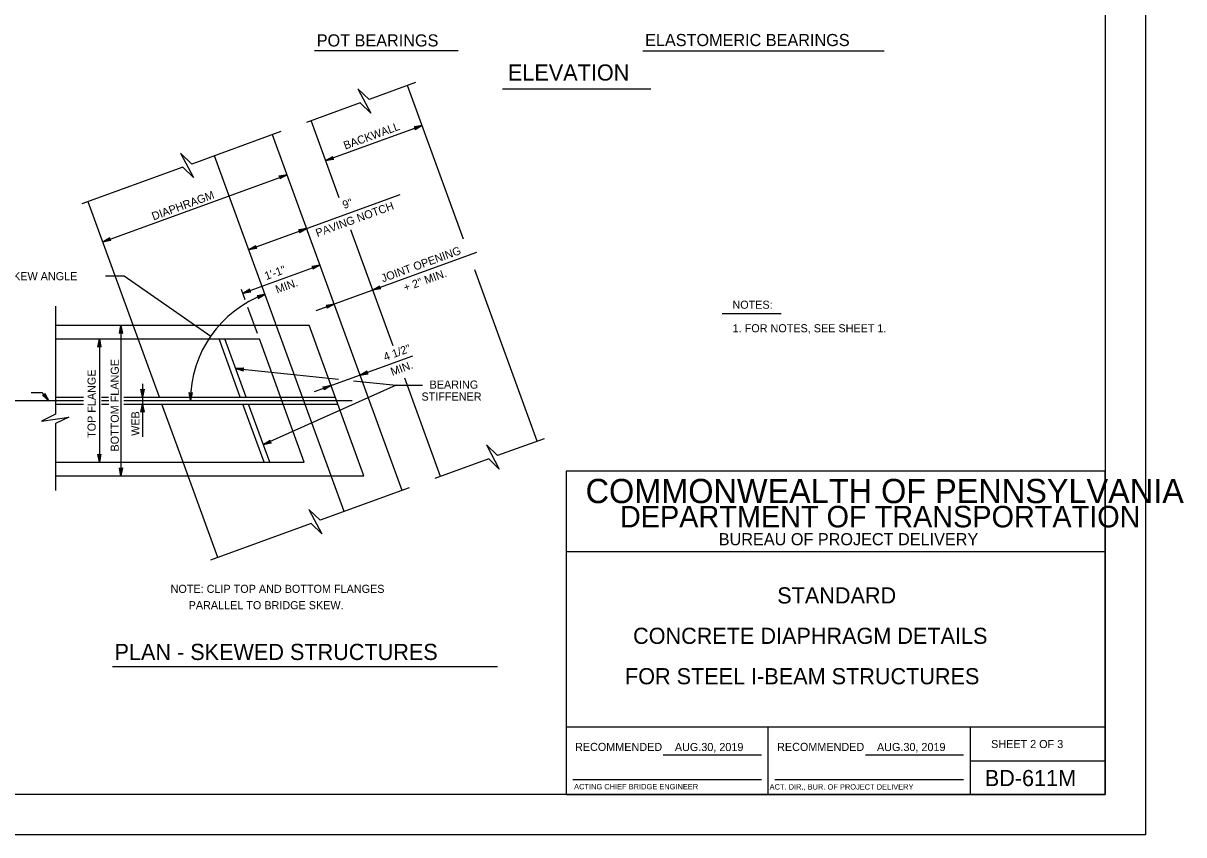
# Model space of a CAD drawing. Extents: x 640009 to 641706, y 298547 to 299735.
# Drawn here: x 641275 to 641705.7, y 299141.2 to 299442.5 of the extents above; entities that cross this region are included whole.
import ezdxf

# ---------------------------------------------------------------- set-up
doc = ezdxf.new("R2010")
doc.units = 0
doc.layers.add('1', color=7, linetype='Continuous')
doc.layers.add('PLT-BNDY', color=7, linetype='Continuous')

msp = doc.modelspace()

# ---------------------------------------------------------------- linework, layer by layer
at = {"layer": '1'}
for p, q in [((641676.47, 299720.17), (641676.47, 299156.17)), ((641676.47, 299720.17), (641676.47, 299156.17)), ((641383.1, 299432.38), (641436.38, 299432.38)), ((641504.95, 299432.23), (641594.55, 299432.23)), ((641420.65, 299420.44), (641403.4, 299414.16)), ((641438.4, 299362.3), (641417.64, 299419.34)), ((641452.84, 299418.18), (641507.99, 299418.18)), ((641400.1, 299412.96), (641380.09, 299405.67)), ((641392.26, 299377.67), (641381.84, 299406.31)), ((641370.64, 299402.24), (641337.56, 299390.2)), ((641387.24, 299391.46), (641423.05, 299404.49)), ((641415.59, 299269.02), (641367.52, 299401.1)), ((641394.11, 299261.2), (641346.04, 299393.28)), ((641334.25, 299388.99), (641296.82, 299375.37)), ((641304.56, 299361.36), (641372.92, 299386.25)), ((641317.7, 299325.25), (641299.15, 299376.22)), ((641358.72, 299358.43), (641414.96, 299378.9)), ((641412.26, 299322.72), (641396.6, 299365.75)), ((641383.76, 299335.82), (641443.42, 299357.53)), ((641356.5, 299342.26), (641385.14, 299352.69)), ((641465.71, 299287.26), (641442.57, 299350.86)), ((641305.6, 299348.64), (641312.45, 299348.64)), ((641312.45, 299348.64), (641344.6, 299326.33)), ((641357.4, 299339.79), (641356.01, 299343.59)), ((641286.98, 299337.48), (641286.98, 299297.33)), ((641361.95, 299327.27), (641358.43, 299336.96)), ((641534.42, 299334.77), (641556.28, 299334.77)), ((641286.98, 299330.32), (641381.11, 299330.32)), ((641311.29, 299330.32), (641311.29, 299274.44)), ((641401.45, 299274.44), (641381.11, 299330.32)), ((641286.98, 299325.25), (641362.69, 299325.25)), ((641303.29, 299325.25), (641303.29, 299279.52)), ((641325.56, 299303.65), (641317.7, 299325.25)), ((641355.59, 299303.65), (641347.74, 299325.25)), ((641357.72, 299303.65), (641349.86, 299325.25)), ((641379.33, 299279.52), (641362.69, 299325.25)), ((641383.16, 299305.7), (641419.57, 299318.95)), ((641353.87, 299314.23), (641392.06, 299310.28)), ((641319.29, 299308.56), (641319.29, 299288.88)), ((641413.39, 299308.08), (641364.14, 299286.03)), ((641397.61, 299309.71), (641413.39, 299308.08)), ((641413.39, 299308.08), (641423.18, 299308.08)), ((641429.91, 299274.23), (641416.62, 299310.75)), ((641277.98, 299305.41), (641281.98, 299305.41)), ((641281.98, 299305.41), (641284.45, 299302.38)), ((641286.98, 299303.65), (641297.34, 299303.65)), ((641304.12, 299303.65), (641306.71, 299303.65)), ((641312.42, 299303.65), (641370.55, 299303.65)), ((641370.55, 299303.65), (641390.82, 299303.65)), ((641262.69, 299302.38), (641297.34, 299302.38)), ((641286.98, 299301.11), (641297.34, 299301.11)), ((641304.12, 299302.38), (641306.84, 299302.38)), ((641304.12, 299301.11), (641306.84, 299301.11)), ((641312.42, 299302.38), (641397.05, 299302.38)), ((641312.42, 299301.11), (641371.47, 299301.11)), ((641334.35, 299279.52), (641326.49, 299301.11)), ((641364.38, 299279.52), (641356.52, 299301.11)), ((641366.51, 299279.52), (641358.65, 299301.11)), ((641371.47, 299301.11), (641391.75, 299301.11)), ((641286.98, 299293.81), (641286.98, 299269.04)), ((641468.3, 299288.2), (641451.06, 299281.93)), ((641286.98, 299279.52), (641379.33, 299279.52)), ((641347.23, 299244.13), (641334.35, 299279.52)), ((641447.75, 299280.72), (641427.74, 299273.44)), ((641286.98, 299274.44), (641401.45, 299274.44)), ((641676.47, 299276.17), (641476.47, 299276.17)), ((641476.47, 299276.17), (641476.47, 299156.17)), ((641676.47, 299276.17), (641476.47, 299276.17)), ((641476.47, 299276.17), (641476.47, 299156.17)), ((641676.47, 299156.17), (641676.47, 299276.17)), ((641676.47, 299156.17), (641676.47, 299276.17)), ((641418.3, 299270), (641385.21, 299257.96)), ((641381.91, 299256.76), (641344.47, 299243.13)), ((641676.47, 299246.17), (641476.47, 299246.17)), ((641676.47, 299246.17), (641476.47, 299246.17)), ((641308.12, 299203.66), (641451.01, 299203.66)), ((641676.47, 299181.17), (641476.47, 299181.17)), ((641676.47, 299181.17), (641476.47, 299181.17)), ((641551.47, 299156.17), (641551.47, 299181.17)), ((641626.47, 299181.17), (641626.47, 299156.17)), ((641626.47, 299181.17), (641626.47, 299156.17)), ((641512.56, 299170.89), (641548.97, 299170.89)), ((641587.56, 299170.89), (641623.97, 299170.89)), ((641626.47, 299168.67), (641676.47, 299168.67)), ((641626.47, 299168.67), (641676.47, 299168.67)), ((641478.97, 299161.67), (641548.97, 299161.67)), ((641553.97, 299161.67), (641623.97, 299161.67)), ((641676.47, 299156.17), (640890.47, 299156.17)), ((641676.47, 299156.17), (640890.47, 299156.17)), ((641476.47, 299156.17), (641676.47, 299156.17)), ((641476.47, 299156.17), (641676.47, 299156.17))]:
    msp.add_line(p, q, dxfattribs=at)
for points in [[(641403.4, 299414.16), (641399.25, 299418.17), (641404.01, 299409.1), (641400.1, 299412.96)], [(641423.05, 299404.49), (641420.43, 299402.95), (641420.52, 299403.06), (641420.6, 299403.17), (641420.62, 299403.29), (641420.64, 299403.4), (641420.62, 299403.5), (641420.6, 299403.6), (641420.55, 299403.69), (641420.5, 299403.78), (641420.41, 299403.85), (641420.32, 299403.93), (641420.19, 299403.96), (641420.05, 299404), (641423.05, 299404.49), (641420.19, 299403.96), (641420.32, 299403.93), (641423.05, 299404.49), (641420.41, 299403.85), (641420.5, 299403.78), (641423.05, 299404.49), (641420.55, 299403.69), (641420.6, 299403.6), (641423.05, 299404.49), (641420.62, 299403.5), (641420.64, 299403.4), (641423.05, 299404.49), (641420.62, 299403.29), (641420.6, 299403.17), (641423.05, 299404.49), (641420.52, 299403.06)], [(641337.56, 299390.2), (641333.4, 299394.2), (641338.17, 299385.14), (641334.25, 299388.99)], [(641387.24, 299391.46), (641389.86, 299393.01), (641389.77, 299392.89), (641389.69, 299392.78), (641389.67, 299392.66), (641389.65, 299392.55), (641389.67, 299392.45), (641389.69, 299392.35), (641389.74, 299392.26), (641389.79, 299392.17), (641389.88, 299392.1), (641389.97, 299392.03), (641390.1, 299391.99), (641390.24, 299391.95), (641387.24, 299391.46), (641390.1, 299391.99), (641389.97, 299392.03), (641387.24, 299391.46), (641389.88, 299392.1), (641389.79, 299392.17), (641387.24, 299391.46), (641389.74, 299392.26), (641389.69, 299392.35), (641387.24, 299391.46), (641389.67, 299392.45), (641389.65, 299392.55), (641387.24, 299391.46), (641389.67, 299392.66), (641389.69, 299392.78), (641387.24, 299391.46), (641389.77, 299392.89)], [(641372.92, 299386.25), (641370.31, 299384.7), (641370.39, 299384.82), (641370.47, 299384.93), (641370.49, 299385.04), (641370.52, 299385.16), (641370.5, 299385.26), (641370.48, 299385.36), (641370.43, 299385.45), (641370.38, 299385.53), (641370.29, 299385.61), (641370.2, 299385.68), (641370.06, 299385.72), (641369.93, 299385.75), (641372.92, 299386.25), (641370.06, 299385.72), (641370.2, 299385.68), (641372.92, 299386.25), (641370.29, 299385.61), (641370.38, 299385.53), (641372.92, 299386.25), (641370.43, 299385.45), (641370.48, 299385.36), (641372.92, 299386.25), (641370.5, 299385.26), (641370.52, 299385.16), (641372.92, 299386.25), (641370.49, 299385.04), (641370.47, 299384.93), (641372.92, 299386.25), (641370.39, 299384.82)], [(641380.2, 299366.25), (641377.59, 299364.71), (641377.67, 299364.82), (641377.75, 299364.93), (641377.77, 299365.05), (641377.79, 299365.16), (641377.78, 299365.26), (641377.76, 299365.36), (641377.71, 299365.45), (641377.66, 299365.54), (641377.57, 299365.61), (641377.48, 299365.69), (641377.34, 299365.72), (641377.21, 299365.76), (641380.2, 299366.25), (641377.34, 299365.72), (641377.48, 299365.69), (641380.2, 299366.25), (641377.57, 299365.61), (641377.66, 299365.54), (641380.2, 299366.25), (641377.71, 299365.45), (641377.76, 299365.36), (641380.2, 299366.25), (641377.78, 299365.26), (641377.79, 299365.16), (641380.2, 299366.25), (641377.77, 299365.05), (641377.75, 299364.93), (641380.2, 299366.25), (641377.67, 299364.82)], [(641304.56, 299361.36), (641307.17, 299362.91), (641307.09, 299362.8), (641307.01, 299362.68), (641306.99, 299362.57), (641306.96, 299362.45), (641306.98, 299362.35), (641307, 299362.25), (641307.05, 299362.17), (641307.1, 299362.08), (641307.19, 299362), (641307.28, 299361.93), (641307.42, 299361.9), (641307.55, 299361.86), (641304.56, 299361.36), (641307.42, 299361.9), (641307.28, 299361.93), (641304.56, 299361.36), (641307.19, 299362), (641307.1, 299362.08), (641304.56, 299361.36), (641307.05, 299362.17), (641307, 299362.25), (641304.56, 299361.36), (641306.98, 299362.35), (641306.96, 299362.45), (641304.56, 299361.36), (641306.99, 299362.57), (641307.01, 299362.68), (641304.56, 299361.36), (641307.09, 299362.8)], [(641358.72, 299358.43), (641361.33, 299359.98), (641361.25, 299359.86), (641361.17, 299359.75), (641361.15, 299359.64), (641361.13, 299359.52), (641361.14, 299359.42), (641361.16, 299359.32), (641361.21, 299359.23), (641361.26, 299359.15), (641361.35, 299359.07), (641361.44, 299359), (641361.58, 299358.96), (641361.71, 299358.93), (641358.72, 299358.43), (641361.58, 299358.96), (641361.44, 299359), (641358.72, 299358.43), (641361.35, 299359.07), (641361.26, 299359.15), (641358.72, 299358.43), (641361.21, 299359.23), (641361.16, 299359.32), (641358.72, 299358.43), (641361.14, 299359.42), (641361.13, 299359.52), (641358.72, 299358.43), (641361.15, 299359.64), (641361.17, 299359.75), (641358.72, 299358.43), (641361.25, 299359.86)], [(641385.14, 299352.69), (641382.53, 299351.14), (641382.61, 299351.26), (641382.69, 299351.37), (641382.71, 299351.48), (641382.73, 299351.6), (641382.71, 299351.7), (641382.69, 299351.8), (641382.64, 299351.89), (641382.59, 299351.97), (641382.5, 299352.05), (641382.41, 299352.12), (641382.28, 299352.16), (641382.14, 299352.19), (641385.14, 299352.69), (641382.28, 299352.16), (641382.41, 299352.12), (641385.14, 299352.69), (641382.5, 299352.05), (641382.59, 299351.97), (641385.14, 299352.69), (641382.64, 299351.89), (641382.69, 299351.8), (641385.14, 299352.69), (641382.71, 299351.7), (641382.73, 299351.6), (641385.14, 299352.69), (641382.71, 299351.48), (641382.69, 299351.37), (641385.14, 299352.69), (641382.61, 299351.26)], [(641356.5, 299342.26), (641359.11, 299343.81), (641359.03, 299343.69), (641358.95, 299343.58), (641358.92, 299343.47), (641358.9, 299343.35), (641358.92, 299343.25), (641358.94, 299343.15), (641358.99, 299343.06), (641359.04, 299342.98), (641359.13, 299342.9), (641359.22, 299342.83), (641359.35, 299342.79), (641359.49, 299342.76), (641356.5, 299342.26), (641359.35, 299342.79), (641359.22, 299342.83), (641356.5, 299342.26), (641359.13, 299342.9), (641359.04, 299342.98), (641356.5, 299342.26), (641358.99, 299343.06), (641358.94, 299343.15), (641356.5, 299342.26), (641358.92, 299343.25), (641358.9, 299343.35), (641356.5, 299342.26), (641358.92, 299343.47), (641358.95, 299343.58), (641356.5, 299342.26), (641359.03, 299343.69)], [(641364.75, 299341.86), (641362.21, 299340.21), (641362.28, 299340.33), (641362.36, 299340.44), (641362.37, 299340.56), (641362.39, 299340.67), (641362.37, 299340.77), (641362.35, 299340.87), (641362.29, 299340.96), (641362.24, 299341.04), (641362.15, 299341.11), (641362.05, 299341.18), (641361.92, 299341.21), (641361.78, 299341.24), (641364.75, 299341.86), (641361.92, 299341.21), (641362.05, 299341.18), (641364.75, 299341.86), (641362.15, 299341.11), (641362.24, 299341.04), (641364.75, 299341.86), (641362.29, 299340.96), (641362.35, 299340.87), (641364.75, 299341.86), (641362.37, 299340.77), (641362.39, 299340.67), (641364.75, 299341.86), (641362.37, 299340.56), (641362.36, 299340.44), (641364.75, 299341.86), (641362.28, 299340.33)], [(641404.72, 299343.45), (641407.33, 299344.99), (641407.25, 299344.88), (641407.17, 299344.76), (641407.15, 299344.65), (641407.13, 299344.54), (641407.14, 299344.44), (641407.16, 299344.34), (641407.21, 299344.25), (641407.26, 299344.16), (641407.35, 299344.09), (641407.44, 299344.01), (641407.58, 299343.98), (641407.71, 299343.94), (641404.72, 299343.45), (641407.58, 299343.98), (641407.44, 299344.01), (641404.72, 299343.45), (641407.35, 299344.09), (641407.26, 299344.16), (641404.72, 299343.45), (641407.21, 299344.25), (641407.16, 299344.34), (641404.72, 299343.45), (641407.14, 299344.44), (641407.13, 299344.54), (641404.72, 299343.45), (641407.15, 299344.65), (641407.17, 299344.76), (641404.72, 299343.45), (641407.25, 299344.88)], [(641390.4, 299338.23), (641387.79, 299336.69), (641387.87, 299336.8), (641387.95, 299336.92), (641387.97, 299337.03), (641387.99, 299337.15), (641387.97, 299337.25), (641387.95, 299337.35), (641387.9, 299337.43), (641387.85, 299337.52), (641387.76, 299337.6), (641387.67, 299337.67), (641387.54, 299337.7), (641387.4, 299337.74), (641390.4, 299338.23), (641387.54, 299337.7), (641387.67, 299337.67), (641390.4, 299338.23), (641387.76, 299337.6), (641387.85, 299337.52), (641390.4, 299338.23), (641387.9, 299337.43), (641387.95, 299337.35), (641390.4, 299338.23), (641387.97, 299337.25), (641387.99, 299337.15), (641390.4, 299338.23), (641387.97, 299337.03), (641387.95, 299336.92), (641390.4, 299338.23), (641387.87, 299336.8)], [(641311.29, 299330.32), (641311.85, 299327.34), (641311.77, 299327.46), (641311.69, 299327.57), (641311.59, 299327.63), (641311.49, 299327.69), (641311.39, 299327.71), (641311.29, 299327.72), (641311.19, 299327.71), (641311.09, 299327.69), (641310.99, 299327.63), (641310.89, 299327.57), (641310.81, 299327.46), (641310.73, 299327.34), (641311.29, 299330.32), (641310.81, 299327.46), (641310.89, 299327.57), (641311.29, 299330.32), (641310.99, 299327.63), (641311.09, 299327.69), (641311.29, 299330.32), (641311.19, 299327.71), (641311.29, 299327.72), (641311.29, 299330.32), (641311.39, 299327.71), (641311.49, 299327.69), (641311.29, 299330.32), (641311.59, 299327.63), (641311.69, 299327.57), (641311.29, 299330.32), (641311.77, 299327.46)], [(641303.29, 299325.25), (641303.85, 299322.26), (641303.77, 299322.38), (641303.69, 299322.49), (641303.59, 299322.55), (641303.49, 299322.61), (641303.39, 299322.63), (641303.29, 299322.65), (641303.19, 299322.63), (641303.09, 299322.61), (641302.99, 299322.55), (641302.89, 299322.49), (641302.81, 299322.38), (641302.73, 299322.26), (641303.29, 299325.25), (641302.81, 299322.38), (641302.89, 299322.49), (641303.29, 299325.25), (641302.99, 299322.55), (641303.09, 299322.61), (641303.29, 299325.25), (641303.19, 299322.63), (641303.29, 299322.65), (641303.29, 299325.25), (641303.39, 299322.63), (641303.49, 299322.61), (641303.29, 299325.25), (641303.59, 299322.55), (641303.69, 299322.49), (641303.29, 299325.25), (641303.77, 299322.38)], [(641353.87, 299314.23), (641356.9, 299314.44), (641356.78, 299314.37), (641356.65, 299314.31), (641356.58, 299314.21), (641356.51, 299314.12), (641356.48, 299314.02), (641356.46, 299313.93), (641356.46, 299313.83), (641356.47, 299313.72), (641356.51, 299313.62), (641356.56, 299313.51), (641356.67, 299313.42), (641356.77, 299313.33), (641353.87, 299314.23), (641356.67, 299313.42), (641356.56, 299313.51), (641353.87, 299314.23), (641356.51, 299313.62), (641356.47, 299313.72), (641353.87, 299314.23), (641356.46, 299313.83), (641356.46, 299313.93), (641353.87, 299314.23), (641356.48, 299314.02), (641356.51, 299314.12), (641353.87, 299314.23), (641356.58, 299314.21), (641356.65, 299314.31), (641353.87, 299314.23), (641356.78, 299314.37)], [(641400.01, 299311.83), (641402.62, 299313.37), (641402.54, 299313.26), (641402.46, 299313.15), (641402.44, 299313.03), (641402.42, 299312.92), (641402.43, 299312.82), (641402.45, 299312.72), (641402.5, 299312.63), (641402.55, 299312.54), (641402.64, 299312.47), (641402.73, 299312.39), (641402.87, 299312.36), (641403, 299312.32), (641400.01, 299311.83), (641402.87, 299312.36), (641402.73, 299312.39), (641400.01, 299311.83), (641402.64, 299312.47), (641402.55, 299312.54), (641400.01, 299311.83), (641402.5, 299312.63), (641402.45, 299312.72), (641400.01, 299311.83), (641402.43, 299312.82), (641402.42, 299312.92), (641400.01, 299311.83), (641402.44, 299313.03), (641402.46, 299313.15), (641400.01, 299311.83), (641402.54, 299313.26)], [(641389.27, 299307.92), (641386.66, 299306.37), (641386.74, 299306.49), (641386.82, 299306.6), (641386.84, 299306.72), (641386.86, 299306.83), (641386.84, 299306.93), (641386.82, 299307.03), (641386.77, 299307.12), (641386.72, 299307.21), (641386.63, 299307.28), (641386.54, 299307.35), (641386.41, 299307.39), (641386.27, 299307.43), (641389.27, 299307.92), (641386.41, 299307.39), (641386.54, 299307.35), (641389.27, 299307.92), (641386.63, 299307.28), (641386.72, 299307.21), (641389.27, 299307.92), (641386.77, 299307.12), (641386.82, 299307.03), (641389.27, 299307.92), (641386.84, 299306.93), (641386.86, 299306.83), (641389.27, 299307.92), (641386.84, 299306.72), (641386.82, 299306.6), (641389.27, 299307.92), (641386.74, 299306.49)], [(641284.45, 299302.38), (641282.13, 299304.34), (641282.26, 299304.3), (641282.4, 299304.26), (641282.51, 299304.28), (641282.63, 299304.3), (641282.72, 299304.35), (641282.81, 299304.4), (641282.87, 299304.47), (641282.94, 299304.55), (641282.98, 299304.66), (641283.02, 299304.77), (641283.01, 299304.91), (641283, 299305.05), (641284.45, 299302.38), (641283.01, 299304.91), (641283.02, 299304.77), (641284.45, 299302.38), (641282.98, 299304.66), (641282.94, 299304.55), (641284.45, 299302.38), (641282.87, 299304.47), (641282.81, 299304.4), (641284.45, 299302.38), (641282.72, 299304.35), (641282.63, 299304.3), (641284.45, 299302.38), (641282.51, 299304.28), (641282.4, 299304.26), (641284.45, 299302.38), (641282.26, 299304.3)], [(641319.29, 299303.65), (641318.73, 299306.64), (641318.81, 299306.52), (641318.89, 299306.41), (641318.99, 299306.35), (641319.09, 299306.29), (641319.19, 299306.27), (641319.29, 299306.25), (641319.39, 299306.27), (641319.49, 299306.29), (641319.59, 299306.35), (641319.69, 299306.41), (641319.77, 299306.52), (641319.85, 299306.64), (641319.29, 299303.65), (641319.77, 299306.52), (641319.69, 299306.41), (641319.29, 299303.65), (641319.59, 299306.35), (641319.49, 299306.29), (641319.29, 299303.65), (641319.39, 299306.27), (641319.29, 299306.25), (641319.29, 299303.65), (641319.19, 299306.27), (641319.09, 299306.29), (641319.29, 299303.65), (641318.99, 299306.35), (641318.89, 299306.41), (641319.29, 299303.65), (641318.81, 299306.52)], [(641337.11, 299302.38), (641336.64, 299305.38), (641336.71, 299305.26), (641336.79, 299305.15), (641336.89, 299305.08), (641336.98, 299305.02), (641337.08, 299305), (641337.18, 299304.98), (641337.28, 299305), (641337.38, 299305.01), (641337.49, 299305.07), (641337.59, 299305.12), (641337.67, 299305.23), (641337.75, 299305.35), (641337.11, 299302.38), (641337.67, 299305.23), (641337.59, 299305.12), (641337.11, 299302.38), (641337.49, 299305.07), (641337.38, 299305.01), (641337.11, 299302.38), (641337.28, 299305), (641337.18, 299304.98), (641337.11, 299302.38), (641337.08, 299305), (641336.98, 299305.02), (641337.11, 299302.38), (641336.89, 299305.08), (641336.79, 299305.15), (641337.11, 299302.38), (641336.71, 299305.26)], [(641319.29, 299301.11), (641319.85, 299298.13), (641319.77, 299298.24), (641319.69, 299298.36), (641319.59, 299298.42), (641319.49, 299298.48), (641319.39, 299298.49), (641319.29, 299298.51), (641319.19, 299298.49), (641319.09, 299298.48), (641318.99, 299298.42), (641318.89, 299298.36), (641318.81, 299298.24), (641318.73, 299298.13), (641319.29, 299301.11), (641318.81, 299298.24), (641318.89, 299298.36), (641319.29, 299301.11), (641318.99, 299298.42), (641319.09, 299298.48), (641319.29, 299301.11), (641319.19, 299298.49), (641319.29, 299298.51), (641319.29, 299301.11), (641319.39, 299298.49), (641319.49, 299298.48), (641319.29, 299301.11), (641319.59, 299298.42), (641319.69, 299298.36), (641319.29, 299301.11), (641319.77, 299298.24)], [(641286.98, 299297.33), (641281.8, 299294.79), (641291.95, 299296.17), (641286.98, 299293.81)], [(641364.14, 299286.03), (641366.68, 299287.69), (641366.6, 299287.57), (641366.53, 299287.45), (641366.51, 299287.34), (641366.49, 299287.22), (641366.52, 299287.13), (641366.54, 299287.03), (641366.59, 299286.94), (641366.65, 299286.85), (641366.74, 299286.79), (641366.83, 299286.72), (641366.97, 299286.69), (641367.11, 299286.66), (641364.14, 299286.03), (641366.97, 299286.69), (641366.83, 299286.72), (641364.14, 299286.03), (641366.74, 299286.79), (641366.65, 299286.85), (641364.14, 299286.03), (641366.59, 299286.94), (641366.54, 299287.03), (641364.14, 299286.03), (641366.52, 299287.13), (641366.49, 299287.22), (641364.14, 299286.03), (641366.51, 299287.34), (641366.53, 299287.45), (641364.14, 299286.03), (641366.6, 299287.57)], [(641451.06, 299281.93), (641446.9, 299285.93), (641451.67, 299276.87), (641447.75, 299280.72)], [(641303.29, 299279.52), (641302.73, 299282.5), (641302.81, 299282.39), (641302.89, 299282.27), (641302.99, 299282.21), (641303.09, 299282.15), (641303.19, 299282.14), (641303.29, 299282.12), (641303.39, 299282.14), (641303.49, 299282.15), (641303.59, 299282.21), (641303.69, 299282.27), (641303.77, 299282.39), (641303.85, 299282.5), (641303.29, 299279.52), (641303.77, 299282.39), (641303.69, 299282.27), (641303.29, 299279.52), (641303.59, 299282.21), (641303.49, 299282.15), (641303.29, 299279.52), (641303.39, 299282.14), (641303.29, 299282.12), (641303.29, 299279.52), (641303.19, 299282.14), (641303.09, 299282.15), (641303.29, 299279.52), (641302.99, 299282.21), (641302.89, 299282.27), (641303.29, 299279.52), (641302.81, 299282.39)], [(641311.29, 299274.44), (641310.73, 299277.42), (641310.81, 299277.31), (641310.89, 299277.19), (641310.99, 299277.14), (641311.09, 299277.08), (641311.19, 299277.06), (641311.29, 299277.04), (641311.39, 299277.06), (641311.49, 299277.08), (641311.59, 299277.14), (641311.69, 299277.19), (641311.77, 299277.31), (641311.85, 299277.42), (641311.29, 299274.44), (641311.77, 299277.31), (641311.69, 299277.19), (641311.29, 299274.44), (641311.59, 299277.14), (641311.49, 299277.08), (641311.29, 299274.44), (641311.39, 299277.06), (641311.29, 299277.04), (641311.29, 299274.44), (641311.19, 299277.06), (641311.09, 299277.08), (641311.29, 299274.44), (641310.99, 299277.14), (641310.89, 299277.19), (641311.29, 299274.44), (641310.81, 299277.31)], [(641385.21, 299257.96), (641381.05, 299261.96), (641385.82, 299252.9), (641381.91, 299256.76)]]:
    msp.add_lwpolyline(points, dxfattribs=at)
msp.add_arc((641379.12, 299302.38), 42.01, 110, 180, dxfattribs=at)
at = {"layer": 'PLT-BNDY'}
msp.add_lwpolyline([(640850.47, 299735.17), (641691.47, 299735.17), (641691.47, 299141.17), (640850.47, 299141.17)], close=True, dxfattribs=at)

# ---------------------------------------------------------------- texts
at = {"layer": '1'}
for s, height, p in [('POT BEARINGS', 4.5, (641383.95, 299433.85)), ('ELASTOMERIC BEARINGS', 4.5, (641505.8, 299433.99)), ('ELEVATION', 6, (641454.9, 299421.18)), ('BEAM SKEW ANGLE', 3, (641256.1, 299347.06)), ('NOTES:', 3, (641538.21, 299336.47)), ('1. FOR NOTES, SEE SHEET 1.', 3, (641538.3, 299327.74)), ('BEARING', 3, (641425.82, 299306.82)), ('STIFFENER', 3, (641422.82, 299302.38)), ('COMMONWEALTH OF PENNSYLVANIA', 9, (641483.72, 299264.3)), ('DEPARTMENT OF TRANSPORTATION', 8.0002, (641496.47, 299255.3)), ('BUREAU OF PROJECT DELIVERY', 4.5, (641533.13, 299248.67)), ('NOTE: CLIP TOP AND BOTTOM FLANGES', 3, (641329.72, 299230.99)), ('STANDARD', 6, (641554.84, 299227.05)), ('      PARALLEL TO BRIDGE SKEW.', 3, (641329.72, 299224.92)), ('CONCRETE DIAPHRAGM DETAILS', 6, (641501.34, 299212.05)), ('PLAN - SKEWED STRUCTURES', 6, (641308.92, 299206.07)), ('FOR STEEL I-BEAM STRUCTURES', 6, (641498.34, 299197.05)), ('RECOMMENDED', 3, (641479.8, 299172.3)), ('AUG.30, 2019', 3, (641516.85, 299172.26)), ('RECOMMENDED', 3, (641554.8, 299172.3)), ('AUG.30, 2019', 3, (641591.85, 299172.26)), ('SHEET 2 OF 3', 3, (641634.21, 299173.37)), ('BD-611M', 6, (641631.86, 299159.24)), ('ACTING CHIEF BRIDGE ENGINEER', 2.0002, (641479.46, 299158.05)), (' ACT. DIR., BUR. OF PROJECT DELIVERY', 2.0002, (641551.24, 299157.96))]:
    msp.add_text(s, height=height, dxfattribs=at).set_placement(p)
for s, rotation, p in [('BACKWALL', 20, (641394.54, 299395.54)), (' DIAPHRAGM', 20, (641322.33, 299368.86)), ('PAVING NOTCH', 20, (641384.18, 299363.05)), ('9"', 20, (641394.14, 299373.47)), ('JOINT OPENING', 20, (641408.48, 299346.23)), ('1\'-1"', 20, (641365.23, 299347.09)), ('+ 2" MIN.', 20, (641416.78, 299342.79)), ('MIN.', 20, (641369.28, 299342.1)), ('4 1/2"', 20, (641409.36, 299317.05)), ('BOTTOM FLANGE', 90, (641310.49, 299283.46)), ('MIN.', 20, (641412, 299311.55)), ('TOP FLANGE', 90, (641301.9, 299288.51)), ('WEB', 90, (641318.14, 299289.29))]:
    msp.add_text(s, height=3, rotation=rotation, dxfattribs=at).set_placement(p)

doc.saveas('drawing.dxf')
